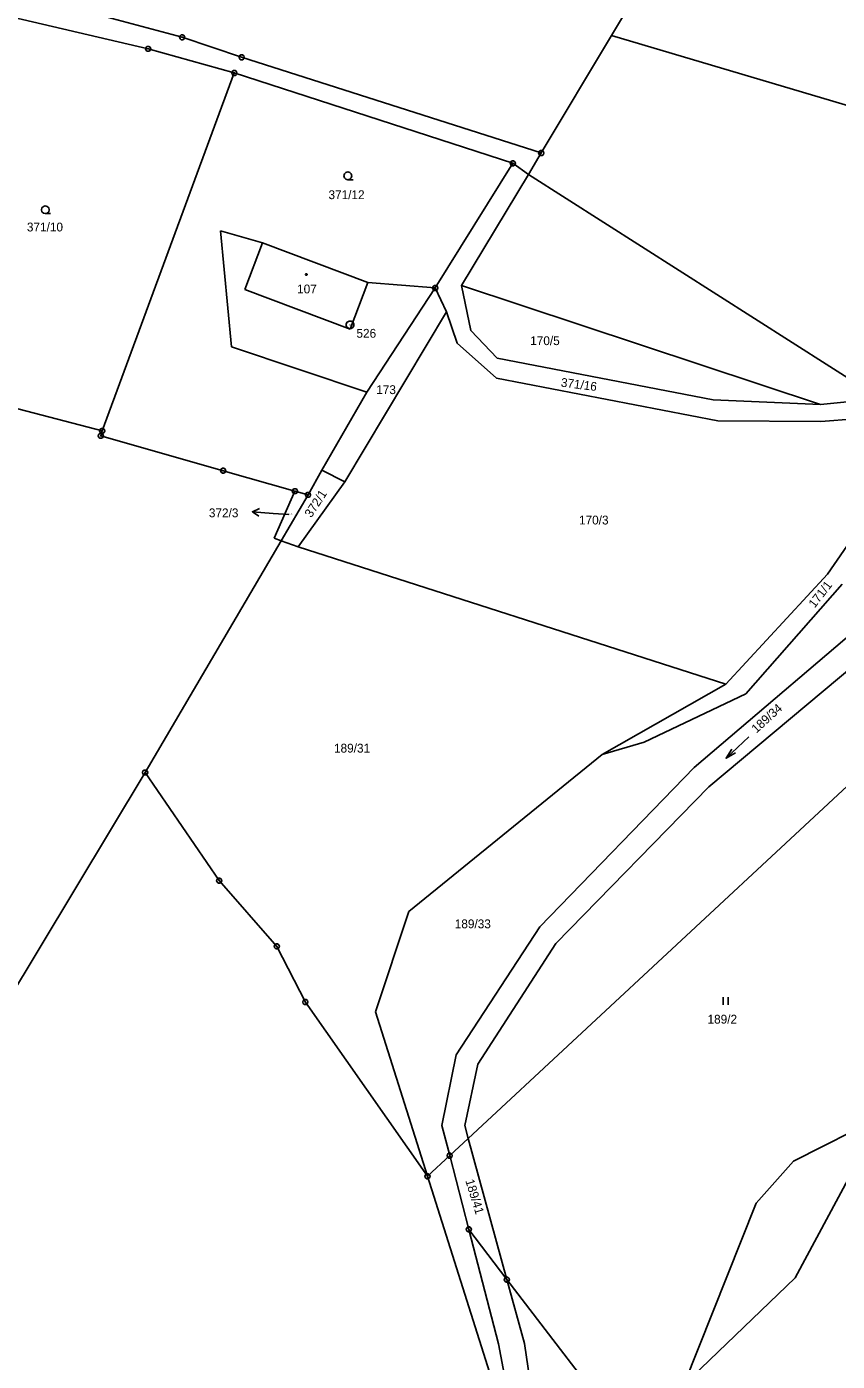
# Model space of a CAD drawing. Extents: x -694465 to -690527, y -983694 to -978978.
# Drawn here: x -693218.8 to -693062.7, y -980627.2 to -980370.2 of the extents above; entities that cross this region are included whole.
import ezdxf

# ---------------------------------------------------------------- set-up
doc = ezdxf.new("R2010")
doc.units = 0
for name, color, linetype in [('Vrstva 1', 7, 'Continuous'), ('Vrstva 16', 7, 'Continuous'), ('Vrstva 17', 7, 'Continuous'), ('Vrstva 18', 7, 'Continuous'), ('Vrstva 19', 7, 'Continuous'), ('Vrstva 24', 7, 'Continuous'), ('Vrstva 25', 7, 'Continuous'), ('Vrstva 29', 7, 'Continuous'), ('Vrstva 60', 7, 'Continuous')]:
    doc.layers.add(name, color=color, linetype=linetype)

msp = doc.modelspace()

# ---------------------------------------------------------------- linework, layer by layer
at = {"layer": 'Vrstva 1'}
for points in [[(-693106.173, -980371.873), (-693088.54, -980342.37)], [(-693225.4, -980367.45), (-693195.39, -980374.43)], [(-693188.84, -980372.2), (-693212.93, -980365.75)], [(-693177.38, -980376.06), (-693188.84, -980372.2)], [(-693119.69, -980394.49), (-693106.173, -980371.873)], [(-693038.46, -980391.96), (-693106.173, -980371.873)], [(-693195.39, -980374.43), (-693178.79, -980379.07)], [(-693119.69, -980394.49), (-693177.38, -980376.06)], [(-693178.79, -980379.07), (-693204.23, -980448)], [(-693178.79, -980379.07), (-693125.16, -980396.48)], [(-693122.169, -980398.606), (-693119.69, -980394.49)], [(-693125.16, -980396.48), (-693140.1, -980420.47)], [(-693135.05, -980419.99), (-693122.169, -980398.606)], [(-693125.16, -980396.48), (-693122.169, -980398.606)], [(-693173.38, -980411.78), (-693181.44, -980409.5)], [(-693181.44, -980409.5), (-693179.31, -980431.84)], [(-693176.77, -980420.78), (-693173.38, -980411.78)], [(-693153.09, -980419.41), (-693173.38, -980411.78)], [(-693156.47, -980428.41), (-693176.77, -980420.78)], [(-693153.09, -980419.41), (-693156.47, -980428.41)], [(-693140.1, -980420.47), (-693153.3, -980440.57)], [(-693140.1, -980420.47), (-693153.09, -980419.41)], [(-693137.93, -980425.06), (-693140.1, -980420.47)], [(-693065.91, -980442.93), (-693135.05, -980419.99)], [(-693135.05, -980419.99), (-693133.27, -980428.66)], [(-693157.49, -980457.85), (-693137.93, -980425.06)], [(-693137.93, -980425.06), (-693135.87, -980431.1)], [(-693133.27, -980428.66), (-693128.15, -980434.02)], [(-693179.31, -980431.84), (-693153.3, -980440.57)], [(-693135.87, -980431.1), (-693128.3, -980437.85)], [(-693128.15, -980434.02), (-693086.61, -980442.04)], [(-693204.23, -980448), (-693248.34, -980436.49)], [(-693128.3, -980437.85), (-693085.71, -980446.05)], [(-693153.3, -980440.57), (-693161.93, -980455.55)], [(-693086.61, -980442.04), (-693065.91, -980442.93)], [(-693054.452, -980441.781), (-693065.91, -980442.93)], [(-693085.71, -980446.05), (-693065.88, -980446.21)], [(-693065.88, -980446.21), (-693059.27, -980445.71)], [(-693204.5, -980448.96), (-693204.23, -980448)], [(-693180.94, -980455.67), (-693204.5, -980448.96)], [(-693167.12, -980459.62), (-693180.94, -980455.67)], [(-693161.93, -980455.55), (-693164.59, -980460.32)], [(-693157.49, -980457.85), (-693161.93, -980455.55)], [(-693167.12, -980459.62), (-693171.1, -980468.67)], [(-693169.77, -980469.15), (-693164.59, -980460.32)], [(-693164.59, -980460.32), (-693167.12, -980459.62)], [(-693166.49, -980470.34), (-693157.49, -980457.85)], [(-693052.55, -980458.18), (-693064.59, -980475.57)], [(-693195.97, -980513.8), (-693169.77, -980469.15)], [(-693171.1, -980468.67), (-693169.77, -980469.15)], [(-693169.77, -980469.15), (-693166.49, -980470.34)], [(-693084.12, -980496.77), (-693166.49, -980470.34)], [(-693064.59, -980475.57), (-693084.12, -980496.77)], [(-693061.74, -980477.54), (-693080.31, -980498.67)], [(-693052.59, -980480.72), (-693090.22, -980512.82)], [(-693087.4, -980516.55), (-693055.95, -980490.26)], [(-693107.93, -980510.3), (-693084.12, -980496.77)], [(-693080.31, -980498.67), (-693099.9, -980507.95)], [(-693133.75, -980584.25), (-693049.78, -980506.25)], [(-693099.9, -980507.95), (-693107.93, -980510.3)], [(-693145.21, -980540.57), (-693107.93, -980510.3)], [(-693222.87, -980558.52), (-693195.97, -980513.8)], [(-693195.97, -980513.8), (-693181.71, -980534.6)], [(-693090.22, -980512.82), (-693119.98, -980543.53)], [(-693116.91, -980546.7), (-693087.4, -980516.55)], [(-693181.71, -980534.6), (-693170.61, -980547.28)], [(-693151.6, -980559.9), (-693145.21, -980540.57)], [(-693119.98, -980543.53), (-693136.05, -980568.14)], [(-693170.61, -980547.28), (-693165.11, -980558.01)], [(-693131.92, -980569.96), (-693116.91, -980546.7)], [(-693165.11, -980558.01), (-693141.59, -980591.54)], [(-693141.59, -980591.54), (-693151.6, -980559.9)], [(-693136.05, -980568.14), (-693138.83, -980581.77)], [(-693134.43, -980581.76), (-693131.92, -980569.96)], [(-693054.11, -980580.07), (-693071.09, -980588.62)], [(-693070.83, -980611.08), (-693054.11, -980580.07)], [(-693138.83, -980581.77), (-693137.32, -980587.57)], [(-693133.75, -980584.25), (-693134.43, -980581.76)], [(-693133.75, -980584.25), (-693137.32, -980587.57)], [(-693126.31, -980611.45), (-693133.75, -980584.25)], [(-693141.59, -980591.54), (-693137.32, -980587.57)], [(-693137.32, -980587.57), (-693133.63, -980601.79)], [(-693071.09, -980588.62), (-693078.3, -980596.72)], [(-693128.83, -980631.9), (-693141.59, -980591.54)], [(-693078.3, -980596.72), (-693092.24, -980631.71)], [(-693133.63, -980601.79), (-693127.9, -980623.84)], [(-693133.63, -980601.79), (-693126.31, -980611.45)], [(-693102.88, -980641.97), (-693126.31, -980611.45)], [(-693122.94, -980623.76), (-693126.31, -980611.45)], [(-693092.24, -980631.71), (-693070.83, -980611.08)], [(-693127.9, -980623.84), (-693125.47, -980636.75)], [(-693120.92, -980637.31), (-693122.94, -980623.76)]]:
    msp.add_lwpolyline(points, dxfattribs=at)
at = {"layer": 'Vrstva 16'}
msp.add_line((-693168.31, -980464.14), (-693171.31, -980463.9), dxfattribs=at)
at = {"layer": 'Vrstva 24'}
for points in [[(-693188.686, -980371.724), (-693188.436, -980371.906), (-693188.34, -980372.2), (-693188.436, -980372.494), (-693188.686, -980372.676), (-693188.994, -980372.676), (-693189.244, -980372.494), (-693189.34, -980372.2), (-693189.244, -980371.906), (-693188.994, -980371.724)], [(-693195.236, -980373.954), (-693194.986, -980374.136), (-693194.89, -980374.43), (-693194.986, -980374.724), (-693195.236, -980374.906), (-693195.544, -980374.906), (-693195.794, -980374.724), (-693195.89, -980374.43), (-693195.794, -980374.136), (-693195.544, -980373.954)], [(-693177.226, -980375.584), (-693176.976, -980375.766), (-693176.88, -980376.06), (-693176.976, -980376.354), (-693177.226, -980376.536), (-693177.534, -980376.536), (-693177.784, -980376.354), (-693177.88, -980376.06), (-693177.784, -980375.766), (-693177.534, -980375.584)], [(-693178.636, -980378.594), (-693178.386, -980378.776), (-693178.29, -980379.07), (-693178.386, -980379.364), (-693178.636, -980379.546), (-693178.944, -980379.546), (-693179.194, -980379.364), (-693179.29, -980379.07), (-693179.194, -980378.776), (-693178.944, -980378.594)], [(-693125.006, -980396.004), (-693124.756, -980396.186), (-693124.66, -980396.48), (-693124.756, -980396.774), (-693125.006, -980396.956), (-693125.314, -980396.956), (-693125.564, -980396.774), (-693125.66, -980396.48), (-693125.564, -980396.186), (-693125.314, -980396.004)], [(-693119.536, -980394.014), (-693119.286, -980394.196), (-693119.19, -980394.49), (-693119.286, -980394.784), (-693119.536, -980394.966), (-693119.844, -980394.966), (-693120.094, -980394.784), (-693120.19, -980394.49), (-693120.094, -980394.196), (-693119.844, -980394.014)], [(-693139.946, -980419.994), (-693139.696, -980420.176), (-693139.6, -980420.47), (-693139.696, -980420.764), (-693139.946, -980420.946), (-693140.254, -980420.946), (-693140.504, -980420.764), (-693140.6, -980420.47), (-693140.504, -980420.176), (-693140.254, -980419.994)], [(-693156.316, -980426.856), (-693155.98, -980427.05), (-693155.786, -980427.386), (-693155.786, -980427.774), (-693155.98, -980428.11), (-693156.316, -980428.304), (-693156.704, -980428.304), (-693157.04, -980428.11), (-693157.234, -980427.774), (-693157.234, -980427.386), (-693157.04, -980427.05), (-693156.704, -980426.856)], [(-693204.346, -980448.484), (-693204.096, -980448.666), (-693204, -980448.96), (-693204.096, -980449.254), (-693204.346, -980449.436), (-693204.654, -980449.436), (-693204.904, -980449.254), (-693205, -980448.96), (-693204.904, -980448.666), (-693204.654, -980448.484)], [(-693204.076, -980447.524), (-693203.826, -980447.706), (-693203.73, -980448), (-693203.826, -980448.294), (-693204.076, -980448.476), (-693204.384, -980448.476), (-693204.634, -980448.294), (-693204.73, -980448), (-693204.634, -980447.706), (-693204.384, -980447.524)], [(-693180.786, -980455.194), (-693180.536, -980455.376), (-693180.44, -980455.67), (-693180.536, -980455.964), (-693180.786, -980456.146), (-693181.094, -980456.146), (-693181.344, -980455.964), (-693181.44, -980455.67), (-693181.344, -980455.376), (-693181.094, -980455.194)], [(-693166.966, -980459.144), (-693166.716, -980459.326), (-693166.62, -980459.62), (-693166.716, -980459.914), (-693166.966, -980460.096), (-693167.274, -980460.096), (-693167.524, -980459.914), (-693167.62, -980459.62), (-693167.524, -980459.326), (-693167.274, -980459.144)], [(-693164.436, -980459.844), (-693164.186, -980460.026), (-693164.09, -980460.32), (-693164.186, -980460.614), (-693164.436, -980460.796), (-693164.744, -980460.796), (-693164.994, -980460.614), (-693165.09, -980460.32), (-693164.994, -980460.026), (-693164.744, -980459.844)], [(-693195.816, -980513.324), (-693195.566, -980513.506), (-693195.47, -980513.8), (-693195.566, -980514.094), (-693195.816, -980514.276), (-693196.124, -980514.276), (-693196.374, -980514.094), (-693196.47, -980513.8), (-693196.374, -980513.506), (-693196.124, -980513.324)], [(-693181.556, -980534.124), (-693181.306, -980534.306), (-693181.21, -980534.6), (-693181.306, -980534.894), (-693181.556, -980535.076), (-693181.864, -980535.076), (-693182.114, -980534.894), (-693182.21, -980534.6), (-693182.114, -980534.306), (-693181.864, -980534.124)], [(-693170.456, -980546.804), (-693170.206, -980546.986), (-693170.11, -980547.28), (-693170.206, -980547.574), (-693170.456, -980547.756), (-693170.764, -980547.756), (-693171.014, -980547.574), (-693171.11, -980547.28), (-693171.014, -980546.986), (-693170.764, -980546.804)], [(-693164.956, -980557.534), (-693164.706, -980557.716), (-693164.61, -980558.01), (-693164.706, -980558.304), (-693164.956, -980558.486), (-693165.264, -980558.486), (-693165.514, -980558.304), (-693165.61, -980558.01), (-693165.514, -980557.716), (-693165.264, -980557.534)], [(-693137.166, -980587.094), (-693136.916, -980587.276), (-693136.82, -980587.57), (-693136.916, -980587.864), (-693137.166, -980588.046), (-693137.474, -980588.046), (-693137.724, -980587.864), (-693137.82, -980587.57), (-693137.724, -980587.276), (-693137.474, -980587.094)], [(-693141.436, -980591.064), (-693141.186, -980591.246), (-693141.09, -980591.54), (-693141.186, -980591.834), (-693141.436, -980592.016), (-693141.744, -980592.016), (-693141.994, -980591.834), (-693142.09, -980591.54), (-693141.994, -980591.246), (-693141.744, -980591.064)], [(-693133.476, -980601.314), (-693133.226, -980601.496), (-693133.13, -980601.79), (-693133.226, -980602.084), (-693133.476, -980602.266), (-693133.784, -980602.266), (-693134.034, -980602.084), (-693134.13, -980601.79), (-693134.034, -980601.496), (-693133.784, -980601.314)], [(-693126.156, -980610.974), (-693125.906, -980611.156), (-693125.81, -980611.45), (-693125.906, -980611.744), (-693126.156, -980611.926), (-693126.464, -980611.926), (-693126.714, -980611.744), (-693126.81, -980611.45), (-693126.714, -980611.156), (-693126.464, -980610.974)]]:
    msp.add_lwpolyline(points, close=True, dxfattribs=at)
for points in [[(-693188.959, -980372.2), (-693188.72, -980372.2)], [(-693195.509, -980374.43), (-693195.27, -980374.43)], [(-693177.499, -980376.06), (-693177.26, -980376.06)], [(-693178.909, -980379.07), (-693178.67, -980379.07)], [(-693119.809, -980394.49), (-693119.57, -980394.49)], [(-693125.279, -980396.48), (-693125.04, -980396.48)], [(-693140.219, -980420.47), (-693139.98, -980420.47)], [(-693156.56, -980427.58), (-693156.46, -980427.58)], [(-693204.619, -980448.96), (-693204.38, -980448.96)], [(-693204.349, -980448), (-693204.11, -980448)], [(-693181.059, -980455.67), (-693180.82, -980455.67)], [(-693167.239, -980459.62), (-693167, -980459.62)], [(-693164.709, -980460.32), (-693164.47, -980460.32)], [(-693196.089, -980513.8), (-693195.85, -980513.8)], [(-693181.829, -980534.6), (-693181.59, -980534.6)], [(-693170.729, -980547.28), (-693170.49, -980547.28)], [(-693165.229, -980558.01), (-693164.99, -980558.01)], [(-693137.439, -980587.57), (-693137.2, -980587.57)], [(-693141.709, -980591.54), (-693141.47, -980591.54)], [(-693133.749, -980601.79), (-693133.51, -980601.79)], [(-693126.429, -980611.45), (-693126.19, -980611.45)]]:
    msp.add_lwpolyline(points, dxfattribs=at)
at = {"layer": 'Vrstva 25'}
for points in [[(-693156.93, -980399.64), (-693157.305, -980399.539), (-693157.579, -980399.265), (-693157.68, -980398.89), (-693157.579, -980398.515), (-693157.305, -980398.241), (-693156.93, -980398.14), (-693156.555, -980398.241), (-693156.281, -980398.515), (-693156.18, -980398.89), (-693156.281, -980399.265), (-693156.555, -980399.539), (-693156.93, -980399.64), (-693155.93, -980399.641)], [(-693215.18, -980406.17), (-693215.555, -980406.069), (-693215.829, -980405.795), (-693215.93, -980405.42), (-693215.829, -980405.045), (-693215.555, -980404.771), (-693215.18, -980404.67), (-693214.805, -980404.771), (-693214.531, -980405.045), (-693214.43, -980405.42), (-693214.531, -980405.795), (-693214.805, -980406.069), (-693215.18, -980406.17), (-693214.18, -980406.171)], [(-693079.742, -980506.917), (-693084.098, -980511.043)], [(-693082.302, -980510.031), (-693084.098, -980511.043), (-693082.99, -980509.305)], [(-693084.69, -980557.05), (-693084.69, -980558.55)], [(-693083.69, -980558.55), (-693083.69, -980557.05)]]:
    msp.add_lwpolyline(points, dxfattribs=at)
msp.add_lwpolyline([(-693164.833, -980417.738), (-693164.745, -980417.89), (-693164.833, -980418.042), (-693165.007, -980418.042), (-693165.095, -980417.89), (-693165.007, -980417.738)], close=True, dxfattribs=at)
at = {"layer": 'Vrstva 29'}
for points in [[(-693173.942, -980462.937), (-693175.297, -980463.581)], [(-693171.31, -980463.9), (-693175.297, -980463.581), (-693174.061, -980464.432)]]:
    msp.add_lwpolyline(points, dxfattribs=at)
at = {"layer": 'Vrstva 60'}
msp.add_line((-693054.452, -980441.781), (-693122.169, -980398.606), dxfattribs=at)

# ---------------------------------------------------------------- texts
at = {"layer": 'Vrstva 16'}
msp.add_text('372/3', height=1.7, dxfattribs=at).set_placement((-693183.69, -980464.65))
at = {"layer": 'Vrstva 17'}
msp.add_text('526', height=1.7, dxfattribs=at).set_placement((-693155.273, -980430.07))
at = {"layer": 'Vrstva 18'}
for s, height, p in [('371/12', 1.7, (-693160.657, -980403.38)), ('371/10', 1.7, (-693218.73, -980409.6)), ('170/5', 1.7, (-693121.819, -980431.49)), ('173', 1.7, (-693151.463, -980440.92)), ('372/3', 0.2, (-693168.282, -980464.14)), ('170/3', 1.7, (-693112.419, -980466.03)), ('189/31', 1.7, (-693159.597, -980509.96)), ('189/33', 1.7, (-693136.347, -980543.79)), ('189/2', 1.7, (-693087.676, -980562.15))]:
    msp.add_text(s, height=height, dxfattribs=at).set_placement(p)
for s, rotation, p in [('371/16', 352.82741, (-693115.986, -980439.476)), ('372/1', 56.89471, (-693163.971, -980464.845)), ('171/1', 52.19646, (-693067.05, -980482.226)), ('189/34', 42.28429, (-693078.269, -980506.316)), ('189/41', 287.10915, (-693134.324, -980592.395))]:
    msp.add_text(s, height=1.7, rotation=rotation, dxfattribs=at).set_placement(p)
at = {"layer": 'Vrstva 19'}
msp.add_text('107', height=1.7, dxfattribs=at).set_placement((-693166.703, -980421.53))

doc.saveas('drawing.dxf')
